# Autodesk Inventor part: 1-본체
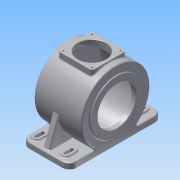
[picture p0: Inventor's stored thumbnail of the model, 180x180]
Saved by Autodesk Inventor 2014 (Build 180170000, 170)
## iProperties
Created: 2015-06
Part Number: 1-본체
Material: 알루미늄 6061
Document SubType Name: Modeling
Designer: Administrator
Density: 2.71 g/cm^3
Appearance: 알루미늄 - 평지
Mass: 3266.43 g
Surface Area: 2316.58 cm^2
Volume: 1205.33 cm^3
Author: Administrator
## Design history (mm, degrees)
sketch "스케치1"
  geometry: L1 (-67, 0)-(67, 0); L2 (-67, 0)-(-67, 65); L3 (-67, 65)-(-54, 65); L4 (-54, 65)-(-54, 85); L5 (-54, 85)-(64, 85); L6 (64, 85)-(64, 65); L7 (64, 65)-(67, 65); L8 (67, 65)-(67, 47.5); L9 (67, 47.5)-(56, 47.5); L10 (56, 47.5)-(56, 77); L11 (56, 77)-(-46, 77); L12 (-46, 77)-(-46, 31); L13 (-46, 31)-(-42.5, 29.368); L14 (-42.5, 29.368)-(-42.5, 23.5); L15 (-42.5, 23.5)-(-56.5, 23.5); L16 (-56.5, 23.5)-(-56.5, 15); L17 (-56.5, 15)-(-59.5, 15); L18 (-59.5, 15)-(-59.5, 0); 2 further points
  constraints: 36 end point, 11 parallel, 3 perpendicular, 1 coincident, 1 collinear, 1 horizontal, 1 midpoint, 1 point on line, 1 vertical, 1 vertical alignment
  dimensions: "d5" = 134 distance of L1.start L1.end; "d6" = 170 diameter of L5 L1; "d7" = 130 diameter of L3 L1; "d8" = 130 diameter of L7 L1; "d9" = 95 diameter of L9 L1; "d10" = 154 diameter of L11 L1; "d11" = 30 diameter of L17 L1; "d12" = 47 diameter of L15 L1; "d13" = 115 deg angle of L13 L12; "d14" = 62 diameter of L12.end L1; "d15" = 14 distance of L14.end L15.end; "d16" = 3 distance of L16.end L17.end; "d17" = 8 distance between parallel lines of L12 L4; "d18" = 8 distance between parallel lines of L6 L10; "d19" = 3.5 horizontal distance of L12.end L13.end; "d20" = 118 distance of L4.end L5.end; "d21" = 11 distance of L8.end L9.end
revolve "회전1" sketch "스케치1" stored, may be unused: angle "d22" = 90 deg
node "작업 평면1"
sketch "스케치2"
  geometry: L1 (46, -115)-(-36, -115); L2 (-54, -97)-(-54, 97); L3 (-36, 115)-(46, 115); L4 (64, 97)-(64, -97); L5 (64, -115)-(-54, 115); L6 (-54, -115)-(64, 115); L7 (-54, -85)-(-54, 85) reference; L8 (64, -85)-(64, 85) reference; L9 (-67, -65)-(-67, 65) reference; A1 r 18 centre (-36, -97) between (-54, -97) and (-36, -115); A2 r 18 centre (46, -97) between (46, -115) and (64, -97); A3 r 18 centre (46, 97) between (64, 97) and (46, 115); A4 r 18 centre (-36, 97) between (-36, 115) and (-54, 97); 3 further points
  constraints: 12 end point, 8 point on circle, 8 point on line, 8 tangent, 4 centre point, 4 midpoint, 3 equal radius, 2 collinear, 2 parallel, 1 horizontal, 1 horizontal alignment, 1 perpendicular
  dimensions: "d26" = 18 radius of A1; "d83" = 230 distance between parallel lines of L1 L3
extrude "돌출2" join sketch "스케치2" distance "d27" = 14; taper "d28" = 0 deg
sketch "스케치7"
  geometry: L1 (64, -97)-(64, -46.733) reference; L2 (-45, -97)-(-45, -81); L3 (-27, -81)-(-27, -97); A1 r 18 centre (-36, -97) between (-54, -97) and (-36, -115) reference; A2 r 9 centre (-36, -81) between (-27, -81) and (-45, -81); A3 r 9 centre (-36, -97) between (-45, -97) and (-27, -97); 1 further point
  constraints: 4 end point, 4 point on circle, 4 tangent, 2 centre point, 2 parallel, 1 coincident
  dimensions: "d58" = 18 distance between parallel lines of L2 L3; "d59" = 16 distance of A2.centre A1.centre
extrude "돌출4" join sketch "스케치7" distance "d60" = 3; taper "d61" = 0 deg
sketch "스케치8"
  geometry: L1 (-45, -81)-(-45, -97) reference; L2 (-27, -97)-(-27, -81) reference; L3 (-40, -97)-(-40, -81); L4 (-32, -81)-(-32, -97); A1 r 9 centre (-36, -97) between (-45, -97) and (-27, -97) reference; A2 r 9 centre (-36, -81) between (-27, -81) and (-45, -81) reference; A3 r 4 centre (-36, -81) between (-32, -81) and (-40, -81); A4 r 4 centre (-36, -97) between (-40, -97) and (-32, -97); 1 further point
  constraints: 4 end point, 4 point on circle, 2 centre point, 3 other
  dimensions: "d62" = 8 distance between parallel lines of L3 L4
extrude "돌출5" cut sketch "스케치8" stored distance "d63" = 3; taper "d64" = 0 deg
sketch "스케치9"
  geometry: L1 (-97, -71)-(-115, -71) reference; L2 (115, -71)-(97, -71) reference; L3 (-109, -71)-(-84.87, -4.703); L4 (109, -71)-(84.87, -4.703); L5 (-115, -85)-(-115, -71) reference; L6 (115, -85)-(115, -71) reference; L7 (-109, -71)-(-46.733, -71); L8 (46.733, -71)-(109, -71); A1 r 85 centre (0, 0) between (-84.87, -4.703) and (84.87, -4.703) reference; 1 further point
  constraints: 8 end point, 4 point on circle, 4 point on line, 1 collinear
  dimensions: "d65" = 110 deg angle of L1 L3; "d66" = 6 distance from line of L3.start L5; "d67" = 110 deg angle of L2 L4; "d68" = 6 distance from line of L4.start L6
extrude "돌출6" join sketch "스케치9" stored distance "d69" = 15; taper "d70" = 0 deg
sketch "스케치10"
  geometry: L1 (29.799, -71)-(-29.799, -71) reference; A1 r 77 centre (0, 0) between (29.799, -71) and (-29.799, -71) reference; 2 further points
  constraints: 1 coincident, 3 other
extrude "돌출7" cut sketch "스케치10" stored distance "d71" = 102; taper "d72" = 0 deg
extrude "돌출8" cut sketch "스케치10" stored distance "d73" = 15; taper "d74" = 0 deg
sketch "스케치11"
  geometry: C1 r 65 at (0, 0) reference; C2 r 47.5 at (0, 0) reference; A1 r 55 centre (0, 0) between (-55, 0) and (0, -55); 2 further points
  constraints: 4 point on circle, 2 horizontal alignment, 2 vertical alignment, 1 centre point, 1 coincident
  dimensions: "d75" = 110 diameter of A1
hole "구멍3" sketch "스케치11" at (-55, 0), (0, -55), (0, 55), (55, 0) diameter "d76" = 3.242; stored, may be unused: countersink angle "d80" = 90 deg, drill point angle "d82" = 0 deg; dims "d77" = 10, "d78" = 4, "d79" = 2, "d81" = 13
fillet "모깎기1" dims "d84" = 3
fillet "모깎기2" dims "d85" = 3
fillet "모깎기3" dims "d86" = 3
fillet "모깎기4" dims "d87" = 3
fillet "모깎기5" dims "d88" = 3
node "작업 평면5"
  node "작업 평면4"
sketch "스케치12"
  geometry: 2 further points
  constraints: 1 coincident, 1 other
feature "엠보싱1" sketch "스케치12" dims "d5" = 134, "d92" = 1, "d93" = 0
fillet "모깎기7" dims "d94" = 3
fillet "모깎기8" dims "d95" = 0.3
fillet "모깎기9" dims "d96" = 3
chamfer "모따기1" distance "d97" = 1; stored, may be unused: second distance "d98" = 2, angle "d99" = 45 deg
node "작업 평면6"
sketch "스케치14"
  geometry: L1 (-47.5, -42.5)-(37.5, -42.5); L2 (37.5, -42.5)-(37.5, 42.5); L3 (37.5, 42.5)-(-47.5, 42.5); L4 (-47.5, 42.5)-(-47.5, -42.5); L5 (-47.5, -42.5)-(37.5, 42.5); L6 (37.5, -42.5)-(-47.5, 42.5); L7 (-46, 115)-(36, 115) reference; L8 (67, 62)-(67, -62) reference; 5 further points
  constraints: 12 end point, 5 midpoint, 2 parallel, 2 perpendicular, 1 horizontal, 1 horizontal alignment, 1 vertical alignment
  dimensions: "d122" = 85 distance of L1.end L2.end
extrude "돌출9" join sketch "스케치14" stored distance "d123" = 10; taper "d124" = 0 deg
fillet "모깎기11" dims "d125" = 7
sketch "스케치15"
  geometry: A1 r 7 centre (40.5, 35.5) between (47.5, 35.5) and (40.5, 42.5) reference; A2 r 7 centre (-30.5, 35.5) between (-30.5, 42.5) and (-37.5, 35.5) reference; A3 r 7 centre (-30.5, -35.5) between (-37.5, -35.5) and (-30.5, -42.5) reference; A4 r 7 centre (40.5, -35.5) between (40.5, -42.5) and (47.5, -35.5) reference; 5 further points
  constraints: 4 coincident
hole "구멍6" sketch "스케치15" at (-30.5, 35.5), (-30.5, -35.5), (40.5, -35.5), (40.5, 35.5) diameter "d126" = 3.242; stored, may be unused: countersink angle "d130" = 90 deg, drill point angle "d132" = 118 deg; dims "d127" = 10, "d128" = 4, "d129" = 2, "d131" = 13
sketch "스케치16"
  geometry: L1 (-30.5, 42.5)-(40.5, 42.5) reference; 3 further points
  constraints: 1 horizontal alignment, 1 midpoint, 1 vertical alignment
hole "구멍7" sketch "스케치16" at (5, 0) diameter "d133" = 70; stored, may be unused: countersink angle "d137" = 90 deg, drill point angle "d139" = 118 deg; dims "d134" = 10, "d135" = 4, "d136" = 2, "d138" = 13
chamfer "모따기3" distance "d140" = 1; stored, may be unused: second distance "d141" = 2, angle "d142" = 45 deg
fillet "모깎기12" dims "d143" = 3
node "솔리드2"
mirror "대칭1"
mirror "대칭2"
node "작업 평면3"
other parameters: "d23" = -85, "d90" = -65 deg, "d91" = 0.5, "d121" = -173
